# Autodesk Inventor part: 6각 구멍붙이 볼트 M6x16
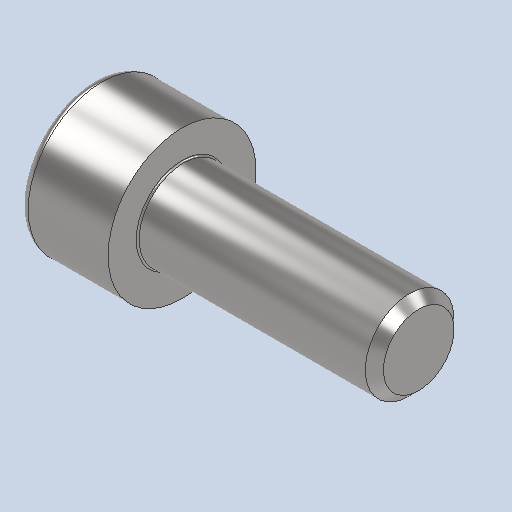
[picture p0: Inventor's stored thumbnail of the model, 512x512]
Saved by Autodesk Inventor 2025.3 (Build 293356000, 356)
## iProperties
Created: 2025-10
Part Number: 6각 구멍붙이 볼트 M6x16
Material: 강철, 연강
Description: 6각머리 태핑 나사
Document SubType Name: Modeling
Designer: PC-04
Density: 7.85 g/cm^3
Appearance: 기본값
Author: jhkim
Sending System: Autodesk Inventor 2026
Preprocessor: ST-DEVELOPER v20.1
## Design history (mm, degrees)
feature "Solid1"
node "솔리드1"
